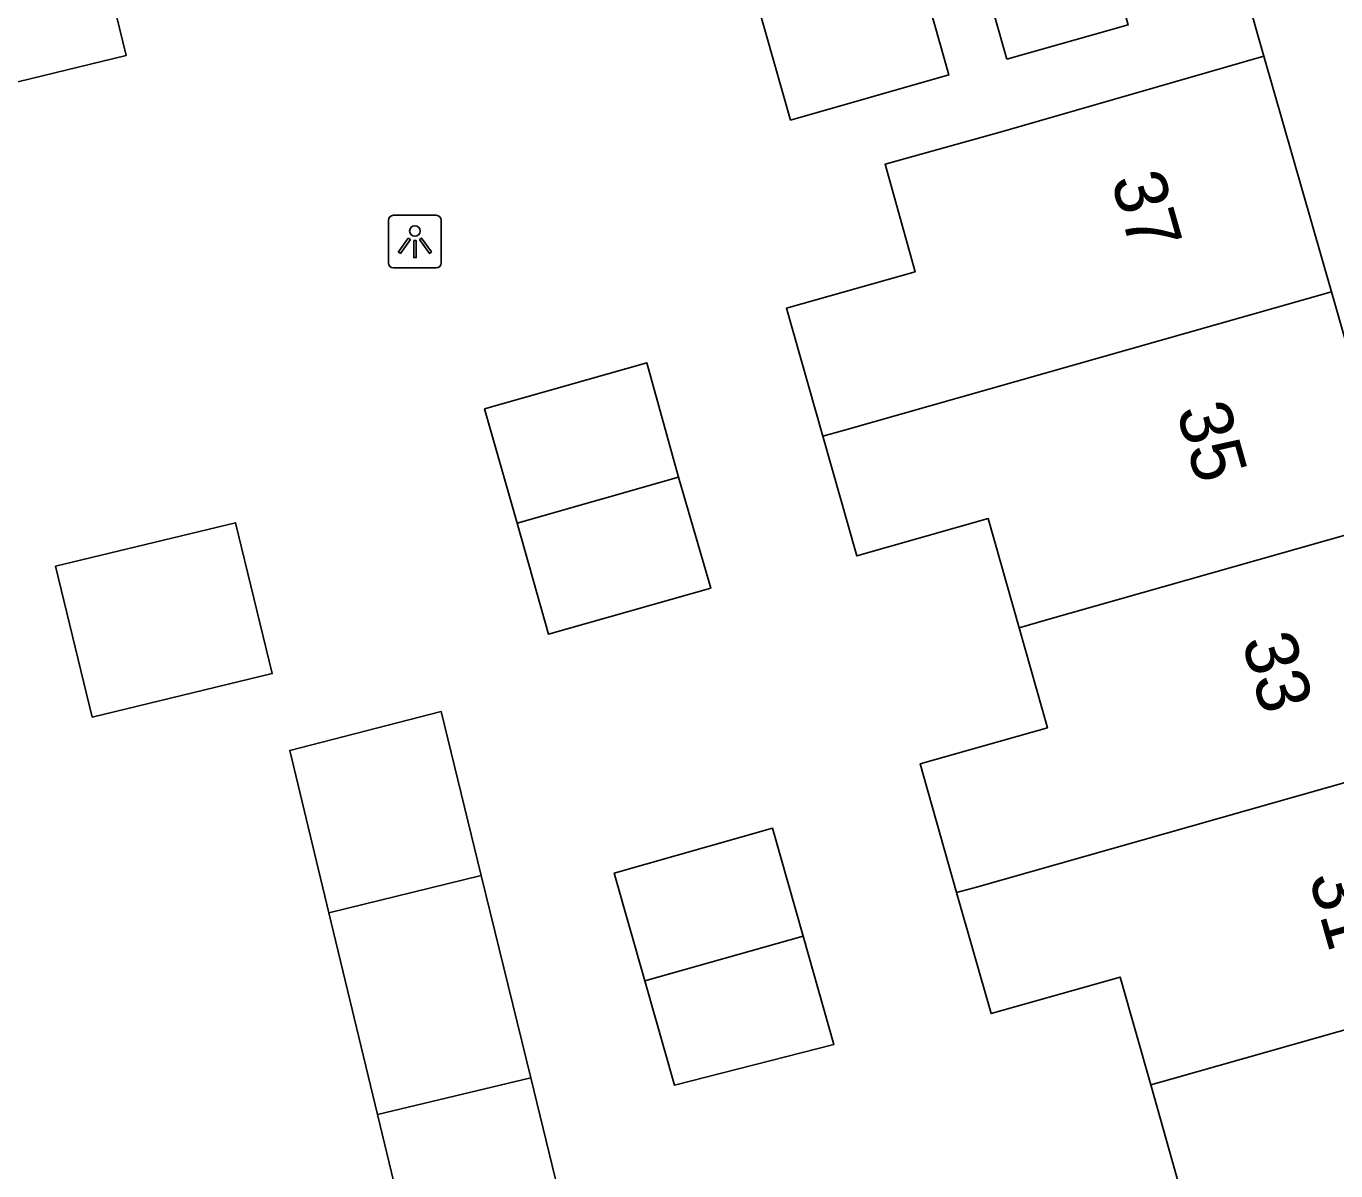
# Model space of a CAD drawing. Extents: x 159718 to 160783, y 383290 to 384030.
# Drawn here: x 160253.65 to 160278.43, y 383535.3 to 383556.96 of the extents above; entities that cross this region are included whole.
import ezdxf

# ---------------------------------------------------------------- set-up
doc = ezdxf.new("R2010")
doc.units = 0
for name, color, linetype in [('IMGEO_Lichtpunt', 7, 'Continuous'), ('IMGEO_Pand', 7, 'Continuous'), ('IMGEO_Pand_nummerreeks', 7, 'Continuous'), ('IMGEO_Voetpad_open', 7, 'Continuous')]:
    doc.layers.add(name, color=color, linetype=linetype)

msp = doc.modelspace()

# ---------------------------------------------------------------- linework, layer by layer
at = {"layer": 'IMGEO_Lichtpunt'}
for p, q in [((160260.506, 383553.283), (160260.506, 383552.476)), ((160260.506, 383553.283), (160260.506, 383552.476)), ((160261.408, 383553.378), (160260.6, 383553.378)), ((160261.408, 383553.378), (160260.6, 383553.378)), ((160261.502, 383552.476), (160261.502, 383553.283)), ((160261.502, 383552.476), (160261.502, 383553.283)), ((160260.6, 383552.382), (160261.408, 383552.382)), ((160260.6, 383552.382), (160261.408, 383552.382))]:
    msp.add_line(p, q, dxfattribs=at)
for points in [[(160260.88, 383552.947), (160260.919, 383552.919), (160260.731, 383552.657), (160260.693, 383552.684), (160260.88, 383552.947)], [(160260.982, 383552.899), (160261.029, 383552.899), (160261.029, 383552.577), (160260.982, 383552.577), (160260.982, 383552.899)], [(160261.092, 383552.919), (160261.13, 383552.946), (160261.317, 383552.684), (160261.278, 383552.656), (160261.092, 383552.919)]]:
    msp.add_lwpolyline(points, dxfattribs=at)
msp.add_circle((160261.005, 383553.081), 0.0994, dxfattribs=at)
for centre, start, end in [((160260.6, 383553.283), 90, 180), ((160260.6, 383553.283), 90, 180), ((160261.408, 383553.283), 0, 90), ((160261.408, 383553.283), 0, 90), ((160260.6, 383552.476), 180, 270), ((160260.6, 383552.476), 180, 270), ((160261.408, 383552.476), 270, 0), ((160261.408, 383552.476), 270, 360)]:
    msp.add_arc(centre, 0.0946, start, end, dxfattribs=at)
at = {"layer": 'IMGEO_Pand'}
for points in [[(160247.938, 383563.021), (160253.602, 383564.398), (160254.936, 383564.722), (160255.889, 383560.792), (160254.554, 383560.468), (160254.781, 383559.534), (160255.541, 383556.399), (160249.88, 383555.027)], [(160272.203, 383556.33), (160271.566, 383558.576), (160273.863, 383559.227), (160274.5, 383556.981), (160272.203, 383556.33)], [(160268.108, 383555.181), (160271.109, 383556.033), (160270.481, 383558.247), (160267.48, 383557.396), (160268.108, 383555.181)], [(160268.721, 383549.198), (160268.034, 383551.618), (160270.468, 383552.309), (160269.9, 383554.344), (160272.122, 383554.966), (160277.064, 383556.388)], [(160278.343, 383551.929), (160277.064, 383556.388)], [(160268.721, 383549.198), (160269.134, 383549.315), (160278.343, 383551.929)], [(160279.583, 383547.604), (160278.343, 383551.929)], [(160262.937, 383547.556), (160262.324, 383549.716), (160265.391, 383550.587), (160265.99, 383548.423)], [(160272.436, 383545.576), (160271.851, 383547.639), (160269.363, 383546.933), (160268.721, 383549.198)], [(160265.99, 383548.423), (160266.601, 383546.324), (160263.534, 383545.453), (160262.937, 383547.556)], [(160265.99, 383548.423), (160262.937, 383547.556)], [(160254.208, 383546.737), (160257.613, 383547.562), (160258.305, 383544.708), (160254.9, 383543.883), (160254.208, 383546.737)], [(160279.583, 383547.604), (160272.979, 383545.73), (160272.436, 383545.576)], [(160271.254, 383540.563), (160270.563, 383543.001), (160272.972, 383543.684), (160272.436, 383545.576)], [(160259.379, 383540.179), (160258.637, 383543.254), (160261.5, 383543.99), (160262.26, 383540.884)], [(160280.824, 383543.279), (160271.628, 383540.669), (160271.254, 383540.563)], [(160265.355, 383538.892), (160264.776, 383540.933), (160267.771, 383541.782), (160268.35, 383539.74)], [(160262.26, 383540.884), (160259.379, 383540.179)], [(160262.26, 383540.884), (160263.197, 383537.056)], [(160274.925, 383536.928), (160274.347, 383538.966), (160271.904, 383538.273), (160271.254, 383540.563)], [(160260.298, 383536.368), (160259.379, 383540.179)], [(160268.35, 383539.74), (160268.932, 383537.687), (160265.914, 383536.918), (160265.355, 383538.892)], [(160265.355, 383538.892), (160268.35, 383539.74)], [(160282.064, 383538.954), (160275.329, 383537.043), (160274.925, 383536.928)], [(160263.197, 383537.056), (160264.128, 383533.251), (160261.22, 383532.547), (160260.298, 383536.368)], [(160263.197, 383537.056), (160260.298, 383536.368)], [(160273.71, 383531.906), (160273.01, 383534.373), (160275.453, 383535.066), (160274.925, 383536.928)]]:
    msp.add_lwpolyline(points, dxfattribs=at)
at = {"layer": 'IMGEO_Voetpad_open'}
msp.add_lwpolyline([(160277.064, 383556.388), (160276.741, 383557.524), (160273.488, 383568.945)], dxfattribs=at)

# ---------------------------------------------------------------- texts
at = {"layer": 'IMGEO_Pand_nummerreeks'}
for s, p in [('37', (160274.17, 383554.049)), ('35', (160275.407, 383549.687)), ('33', (160276.644, 383545.325)), ('31', (160277.913, 383540.856))]:
    msp.add_text(s, height=1, rotation=285.8363, dxfattribs=at).set_placement(p)

doc.saveas('drawing.dxf')
